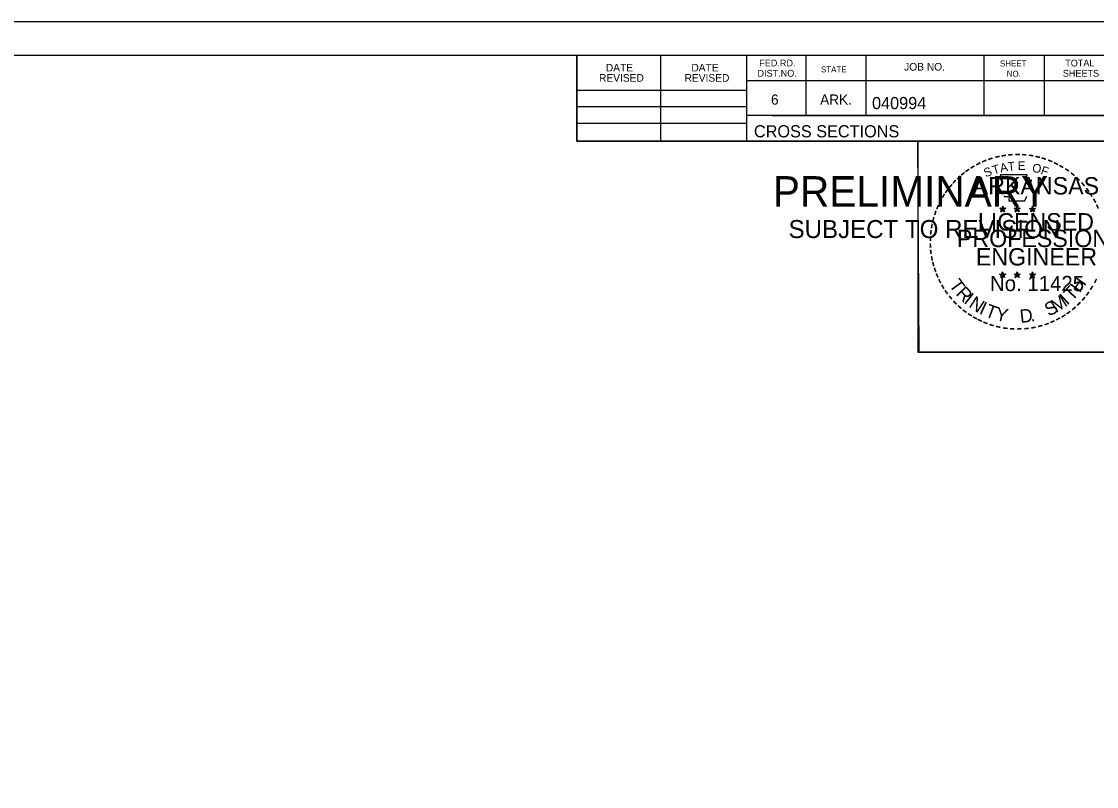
# Model space of a CAD drawing. Extents: x 1381471 to 1382703, y 370300 to 371487.
# Drawn here: x 1382168.2 to 1382292, y 370972.4 to 371060.5 of the extents above; entities that cross this region are included whole.
import ezdxf

# ---------------------------------------------------------------- set-up
doc = ezdxf.new("R2010")
doc.units = 0
doc.layers.add('Level 45', color=7, linetype='Continuous')

msp = doc.modelspace()

# ---------------------------------------------------------------- linework, layer by layer
at = {"layer": 'Level 45'}
for p, q in [((1381966.21, 371060.47), (1382299.55, 371060.47)), ((1381978.61, 371056.58), (1382294.79, 371056.58)), ((1382232.15, 371046.7), (1382232.15, 371056.58)), ((1382241.83, 371046.7), (1382241.83, 371056.58)), ((1382251.69, 371056.58), (1382251.69, 371046.7)), ((1382258.53, 371056.58), (1382258.53, 371049.64)), ((1382265.47, 371056.58), (1382265.47, 371049.64)), ((1382279.05, 371056.58), (1382279.05, 371049.64)), ((1382285.99, 371056.58), (1382285.99, 371049.64)), ((1382294.79, 371053.64), (1382251.69, 371053.64)), ((1382232.15, 371052.56), (1382251.69, 371052.56)), ((1382232.15, 371050.7), (1382251.69, 371050.7)), ((1382232.15, 371048.76), (1382251.69, 371048.76)), ((1382294.79, 371049.64), (1382251.69, 371049.64)), ((1382254.65, 371049.64), (1382294.79, 371049.64)), ((1382294.79, 371046.7), (1382232.15, 371046.7)), ((1382280.88, 371038.96), (1382281.23, 371038.84)), ((1382280.88, 371038.96), (1382281.13, 371038.91)), ((1382280.88, 371038.96), (1382281.12, 371038.83)), ((1382281.01, 371038.55), (1382281.23, 371038.84)), ((1382281.01, 371038.55), (1382281.14, 371038.79)), ((1382281.01, 371038.55), (1382281.23, 371038.76)), ((1382281.23, 371039.21), (1382281.19, 371038.96)), ((1382281.23, 371038.84), (1382281.23, 371039.21)), ((1382281.23, 371039.21), (1382281.28, 371038.96)), ((1382281.57, 371038.96), (1382281.23, 371038.84)), ((1382281.44, 371038.55), (1382281.23, 371038.84)), ((1382281.44, 371038.55), (1382281.23, 371038.76)), ((1382281.57, 371038.96), (1382281.29, 371038.91)), ((1382281.44, 371038.55), (1382281.3, 371038.84)), ((1382281.57, 371038.96), (1382281.37, 371038.85)), ((1382282.55, 371038.96), (1382282.9, 371038.84)), ((1382282.55, 371038.96), (1382282.8, 371038.91)), ((1382282.55, 371038.96), (1382282.79, 371038.83)), ((1382282.68, 371038.55), (1382282.9, 371038.84)), ((1382282.68, 371038.55), (1382282.81, 371038.79)), ((1382282.68, 371038.55), (1382282.9, 371038.76)), ((1382282.9, 371039.21), (1382282.86, 371038.96)), ((1382282.9, 371038.84), (1382282.9, 371039.21)), ((1382282.9, 371039.21), (1382282.95, 371038.96)), ((1382283.24, 371038.96), (1382282.9, 371038.84)), ((1382283.11, 371038.55), (1382282.9, 371038.84)), ((1382283.11, 371038.55), (1382282.9, 371038.76)), ((1382283.24, 371038.96), (1382282.96, 371038.91)), ((1382283.11, 371038.55), (1382282.97, 371038.84)), ((1382283.24, 371038.96), (1382283.04, 371038.85)), ((1382284.31, 371038.94), (1382284.66, 371038.83)), ((1382284.31, 371038.94), (1382284.57, 371038.9)), ((1382284.31, 371038.94), (1382284.55, 371038.82)), ((1382284.45, 371038.54), (1382284.66, 371038.83)), ((1382284.45, 371038.54), (1382284.57, 371038.78)), ((1382284.45, 371038.54), (1382284.66, 371038.75)), ((1382284.66, 371039.2), (1382284.62, 371038.95)), ((1382284.66, 371038.83), (1382284.66, 371039.2)), ((1382284.66, 371039.2), (1382284.71, 371038.95)), ((1382285.01, 371038.94), (1382284.66, 371038.83)), ((1382284.87, 371038.54), (1382284.66, 371038.83)), ((1382284.87, 371038.54), (1382284.66, 371038.75)), ((1382285.01, 371038.94), (1382284.72, 371038.89)), ((1382284.87, 371038.54), (1382284.74, 371038.83)), ((1382285.01, 371038.94), (1382284.8, 371038.84)), ((1382280.87, 371031.38), (1382281.22, 371031.27)), ((1382280.87, 371031.38), (1382281.13, 371031.34)), ((1382280.87, 371031.38), (1382281.11, 371031.26)), ((1382281.01, 371030.97), (1382281.22, 371031.27)), ((1382281.01, 371030.97), (1382281.13, 371031.22)), ((1382281.22, 371031.64), (1382281.18, 371031.38)), ((1382281.22, 371031.27), (1382281.22, 371031.64)), ((1382281.22, 371031.64), (1382281.27, 371031.39)), ((1382281.57, 371031.38), (1382281.22, 371031.27)), ((1382281.44, 371030.97), (1382281.22, 371031.27)), ((1382281.57, 371031.38), (1382281.28, 371031.33)), ((1382281.44, 371030.97), (1382281.3, 371031.27)), ((1382281.57, 371031.38), (1382281.37, 371031.28)), ((1382282.54, 371031.38), (1382282.89, 371031.27)), ((1382282.54, 371031.38), (1382282.8, 371031.34)), ((1382282.54, 371031.38), (1382282.78, 371031.26)), ((1382282.68, 371030.97), (1382282.89, 371031.27)), ((1382282.68, 371030.97), (1382282.8, 371031.22)), ((1382282.89, 371031.64), (1382282.85, 371031.38)), ((1382282.89, 371031.27), (1382282.89, 371031.64)), ((1382282.89, 371031.64), (1382282.94, 371031.39)), ((1382283.24, 371031.38), (1382282.89, 371031.27)), ((1382283.11, 371030.97), (1382282.89, 371031.27)), ((1382283.24, 371031.38), (1382282.95, 371031.33)), ((1382283.11, 371030.97), (1382282.97, 371031.27)), ((1382283.24, 371031.38), (1382283.04, 371031.28)), ((1382284.31, 371031.37), (1382284.66, 371031.26)), ((1382284.31, 371031.37), (1382284.56, 371031.33)), ((1382284.31, 371031.37), (1382284.55, 371031.25)), ((1382284.44, 371030.96), (1382284.66, 371031.26)), ((1382284.66, 371031.63), (1382284.62, 371031.37)), ((1382284.66, 371031.26), (1382284.66, 371031.63)), ((1382284.66, 371031.63), (1382284.71, 371031.38)), ((1382285.01, 371031.37), (1382284.66, 371031.26)), ((1382284.87, 371030.96), (1382284.66, 371031.26)), ((1382285.01, 371031.37), (1382284.72, 371031.32)), ((1382284.87, 371030.96), (1382284.74, 371031.26)), ((1382285.01, 371031.37), (1382284.8, 371031.27)), ((1382281.01, 371030.97), (1382281.22, 371031.19)), ((1382281.44, 371030.97), (1382281.22, 371031.19)), ((1382282.68, 371030.97), (1382282.89, 371031.19)), ((1382283.11, 371030.97), (1382282.89, 371031.19)), ((1382284.44, 371030.96), (1382284.57, 371031.21)), ((1382284.44, 371030.96), (1382284.66, 371031.18)), ((1382284.87, 371030.96), (1382284.66, 371031.18)), ((1382270.83, 371024.24), (1382270.83, 371024.24))]:
    msp.add_line(p, q, dxfattribs=at)
for points in [[(1381966.21, 371060.47), (1382299.55, 371060.47), (1382299.55, 370847.14), (1381966.21, 370847.14)], [(1382212.53, 371056.58), (1382232.15, 371056.58), (1382232.15, 371046.7), (1382248.27, 371046.7), (1382271.46, 371046.7), (1382271.46, 371022.37), (1382294.79, 371022.37), (1382294.79, 370851.12), (1381978.61, 370851.12), (1381978.61, 371056.58)], [(1382271.46, 371046.7), (1382294.67, 371046.7), (1382294.79, 371022.37), (1382271.59, 371022.37)]]:
    msp.add_lwpolyline(points, close=True, dxfattribs=at)
for points in [[(1382280.92, 371042.83), (1382281.19, 371042.01)], [(1382284.43, 371041.91), (1382284.57, 371042.2), (1382283.89, 371042.17), (1382284.04, 371042.83), (1382280.92, 371042.83)], [(1382281.41, 371040.41), (1382281.41, 371040.32), (1382281.97, 371040.3), (1382281.92, 371039.83), (1382283.79, 371039.83), (1382283.99, 371040.37)], [(1382281.23, 371039.21), (1382281.44, 371038.55), (1382280.88, 371038.96), (1382281.57, 371038.96), (1382281.01, 371038.55), (1382281.23, 371039.21)], [(1382282.9, 371039.21), (1382283.11, 371038.55), (1382282.55, 371038.96), (1382283.24, 371038.96), (1382282.68, 371038.55), (1382282.9, 371039.21)], [(1382284.66, 371039.2), (1382284.87, 371038.54), (1382284.31, 371038.94), (1382285.01, 371038.94), (1382284.45, 371038.54), (1382284.66, 371039.2)], [(1382281.22, 371031.64), (1382281.44, 371030.97), (1382280.87, 371031.38), (1382281.57, 371031.38), (1382281.01, 371030.97), (1382281.22, 371031.64)], [(1382282.89, 371031.64), (1382283.11, 371030.97), (1382282.54, 371031.38), (1382283.24, 371031.38), (1382282.68, 371030.97), (1382282.89, 371031.64)], [(1382284.66, 371031.63), (1382284.87, 371030.96), (1382284.31, 371031.37), (1382285.01, 371031.37), (1382284.44, 371030.96), (1382284.66, 371031.63)]]:
    msp.add_lwpolyline(points, dxfattribs=at)
for centre, radius in [((1382281.23, 371038.84), 0.172), ((1382281.23, 371038.84), 0.145), ((1382281.23, 371038.84), 0.116), ((1382281.23, 371038.84), 0.0991), ((1382281.23, 371038.84), 0.0747), ((1382281.23, 371038.84), 0.0495), ((1382281.23, 371038.84), 0.0296), ((1382282.9, 371038.84), 0.172), ((1382282.9, 371038.84), 0.145), ((1382282.9, 371038.84), 0.116), ((1382282.9, 371038.84), 0.0991), ((1382282.9, 371038.84), 0.0747), ((1382282.9, 371038.84), 0.0495), ((1382282.9, 371038.84), 0.0296), ((1382284.66, 371038.83), 0.172), ((1382284.66, 371038.83), 0.145), ((1382284.66, 371038.83), 0.116), ((1382284.66, 371038.83), 0.0991), ((1382284.66, 371038.83), 0.0747), ((1382284.66, 371038.83), 0.0495), ((1382284.66, 371038.83), 0.0296), ((1382281.22, 371031.27), 0.172), ((1382281.22, 371031.27), 0.145), ((1382281.22, 371031.27), 0.116), ((1382281.22, 371031.27), 0.0991), ((1382281.22, 371031.27), 0.0747), ((1382281.22, 371031.27), 0.0495), ((1382281.22, 371031.27), 0.0296), ((1382282.89, 371031.27), 0.172), ((1382282.89, 371031.27), 0.145), ((1382282.89, 371031.27), 0.116), ((1382282.89, 371031.27), 0.0991), ((1382282.89, 371031.27), 0.0747), ((1382282.89, 371031.27), 0.0495), ((1382282.89, 371031.27), 0.0296), ((1382284.66, 371031.26), 0.172), ((1382284.66, 371031.26), 0.145), ((1382284.66, 371031.26), 0.116), ((1382284.66, 371031.26), 0.0991), ((1382284.66, 371031.26), 0.0747), ((1382284.66, 371031.26), 0.0495), ((1382284.66, 371031.26), 0.0296)]:
    msp.add_circle(centre, radius, dxfattribs=at)

# ---------------------------------------------------------------- texts
for s, height, rotation, p in [('FED.RD.', 0.782, 360, (1382253.17, 371055.3)), ('SHEET', 0.684, 360, (1382280.91, 371055.3)), ('TOTAL', 0.782, 360, (1382288.43, 371055.3)), ('DATE', 0.879, 360, (1382235.49, 371054.72)), ('DATE', 0.879, 360, (1382245.35, 371054.72)), ('DIST.NO.', 0.782, 360, (1382252.97, 371054.12)), ('STATE', 0.684, 360, (1382260.29, 371054.62)), ('JOB NO.', 0.879, 360, (1382269.87, 371054.82)), ('NO.', 0.684, 360, (1382281.69, 371054.12)), ('SHEETS', 0.782, 360, (1382288.15, 371054.12)), ('REVISED', 0.879, 360, (1382234.71, 371053.54)), ('REVISED', 0.879, 360, (1382244.57, 371053.54)), ('6', 1.17, 360, (1382254.53, 371050.9)), ('ARK.', 1.172, 360, (1382260.19, 371050.9)), ('040994', 1.4, 360, (1382266.17, 371050.38)), ('CROSS SECTIONS', 1.4, 360, (1382252.56, 371047.13)), ('-', 1.6, 13.6301, (1382280.42, 371044.2)), ('-', 1.6, 10.2193, (1382281.1, 371044.36)), ('-', 1.6, 5.8968, (1382281.82, 371044.47)), ('-', 1.6, 0.1862, (1382282.6, 371044.55)), ('-', 1.6, 357.743, (1382283.32, 371044.53)), ('-', 1.6, 352.1617, (1382284.06, 371044.48)), ('-', 1.6, 347.2049, (1382284.78, 371044.36)), ('-', 1.6, 342.3362, (1382285.42, 371044.21)), ('-', 1.6, 34.0636, (1382277.8, 371043)), ('-', 1.6, 28.7918, (1382278.4, 371043.37)), ('-', 1.6, 24.3072, (1382279.03, 371043.69)), ('S', 1, 21.594, (1382279.27, 371042.51)), ('-', 1.6, 19.1761, (1382279.67, 371043.96)), ('T', 1, 16.4036, (1382280.19, 371042.84)), ('A', 1, 11.2132, (1382281.01, 371043.09)), ('T', 1, 6.0228, (1382281.86, 371043.26)), ('E', 1, 0.8323, (1382282.97, 371043.37)), ('O', 1, 350.4515, (1382284.57, 371043.16)), ('F', 1, 340.0707, (1382285.53, 371042.93)), ('-', 1.6, 337.8551, (1382286.15, 371043.98)), ('-', 1.6, 334.1211, (1382286.78, 371043.71)), ('-', 1.6, 329.6409, (1382287.36, 371043.43)), ('-', 1.6, 325.8627, (1382288.01, 371043.07)), ('PRELIMINARY', 3.5, 360, (1382254.74, 371039.16)), ('-', 1.6, 42.9622, (1382276.32, 371041.81)), ('-', 1.6, 38.9507, (1382276.75, 371042.23)), ('-', 1.6, 36.2317, (1382277.23, 371042.61)), ('ARKANSAS', 2, 360, (1382277.77, 371040.55)), ('-', 1.6, 320.5297, (1382288.62, 371042.64)), ('-', 1.6, 315.5786, (1382289.21, 371042.16)), ('-', 1.6, 54.2325, (1382275.05, 371040.28)), ('-', 1.6, 50.6142, (1382275.47, 371040.85)), ('-', 1.6, 48.423, (1382275.87, 371041.34)), ('-', 1.6, 309.8797, (1382289.78, 371041.61)), ('-', 1.6, 306.6522, (1382290.31, 371041)), ('DWB', 0.01, 360, (1382255.49, 371041.01)), ('-', 1.6, 62.8713, (1382274.41, 371039.14)), ('-', 1.6, 58.0706, (1382274.73, 371039.76)), ('-', 1.4, 303.6753, (1382290.79, 371040.44)), ('-', 1.6, 299.6684, (1382291.11, 371039.83)), ('-', 1.6, 72.3945, (1382273.94, 371037.9)), ('-', 1.6, 67.7743, (1382274.16, 371038.53)), ('DWB', 0.01, 360, (1382281.21, 371038.84)), ('DWB', 0.01, 360, (1382282.88, 371038.84)), ('DWB', 0.01, 360, (1382284.65, 371038.83)), ('-', 1.6, 294.6628, (1382291.44, 371039.22)), ('SUBJECT TO REVISION', 2.0751, 360, (1382256.55, 371035.53)), ('-', 1.6, 75.461, (1382273.74, 371037.19)), ('LICENSED', 2, 360, (1382278.37, 371036.4)), ('-', 1.6, 85.1863, (1382273.53, 371035.78)), ('-', 1.6, 81.2013, (1382273.61, 371036.47)), ('PROFESSIONAL', 2, 360, (1382275.95, 371034.49)), ('-', 1.6, 94.1959, (1382273.54, 371034.36)), ('-', 1.6, 89.0622, (1382273.51, 371035.08)), ('-', 1.6, 98.9479, (1382273.61, 371033.69)), ('ENGINEER', 2, 360, (1382278.13, 371032.37)), ('-', 1.6, 101.7149, (1382273.75, 371032.96)), ('-', 1.6, 105.4578, (1382273.91, 371032.36)), ('-', 1.6, 109.0874, (1382274.13, 371031.73)), ('-', 1.6, 114.0643, (1382274.38, 371031.14)), ('DWB', 0.01, 360, (1382281.21, 371031.27)), ('DWB', 0.01, 360, (1382282.88, 371031.27)), ('DWB', 0.01, 360, (1382284.65, 371031.26)), ('-', 1.6, 115.7289, (1382274.68, 371030.52)), ('-', 1.6, 120.4471, (1382275.04, 371029.93)), ('T', 1.54, 306.0406, (1382274.98, 371030.11)), ('R', 1.54, 314.005, (1382275.75, 371029.06)), ('No. 11425', 1.757, 360, (1382279.76, 371029.42)), ('T', 1.54, 46.6444, (1382289.21, 371028.2)), ('H', 1.54, 54.6088, (1382290.1, 371029.14)), ('-', 1.6, 239.0712, (1382291.12, 371030.42)), ('-', 1.6, 244.6197, (1382291.52, 371031.18)), ('-', 1.6, 125.8934, (1382275.44, 371029.37)), ('-', 1.6, 130.7181, (1382275.91, 371028.82)), ('I', 1.54, 321.9694, (1382276.65, 371028.13)), ('N', 1.54, 326.5002, (1382277.21, 371027.66)), ('M', 1.54, 32.6563, (1382287.37, 371026.88)), ('I', 1.54, 42.1136, (1382288.65, 371027.72)), ('-', 1.6, 231.2538, (1382290.29, 371029.2)), ('-', 1.6, 233.8452, (1382290.72, 371029.77)), ('-', 1.6, 134.2238, (1382276.42, 371028.27)), ('-', 1.6, 138.9338, (1382276.95, 371027.81)), ('I', 1.54, 335.3603, (1382278.42, 371026.87)), ('T', 1.54, 339.8912, (1382279.08, 371026.54)), ('Y', 1.54, 347.8556, (1382280.3, 371026.1)), ('S', 1.54, 26.9312, (1382286.53, 371026.47)), ('-', 1.6, 221.0851, (1382289.29, 371028.13)), ('-', 1.6, 225.7653, (1382289.81, 371028.64)), ('-', 1.6, 144.6463, (1382277.5, 371027.4)), ('-', 1.6, 148.0898, (1382278.07, 371027.03)), ('-', 1.6, 151.5704, (1382278.64, 371026.71)), ('D', 1.54, 6.3969, (1382283.28, 371025.74)), ('-', 1.6, 207.3568, (1382287.65, 371026.93)), ('-', 1.6, 212.2491, (1382288.21, 371027.27)), ('-', 1.6, 215.7363, (1382288.74, 371027.66)), ('-', 1.6, 154.6002, (1382279.17, 371026.46)), ('-', 1.6, 158.5612, (1382279.79, 371026.21)), ('-', 1.6, 162.7983, (1382280.48, 371025.99)), ('-', 1.6, 167.5555, (1382281.19, 371025.83)), ('-', 1.6, 173.1155, (1382281.96, 371025.72)), ('-', 1.6, 176.5183, (1382282.71, 371025.67)), ('-', 1.6, 181.5918, (1382283.46, 371025.69)), ('-', 1.6, 185.8167, (1382284.27, 371025.76)), ('-', 1.6, 191.2858, (1382285, 371025.89)), ('.', 1.54, 13.7642, (1382284.48, 371025.87)), ('-', 1.6, 195.4743, (1382285.73, 371026.09)), ('-', 1.6, 200.7184, (1382286.41, 371026.33)), ('-', 1.6, 204.2516, (1382287.03, 371026.61))]:
    msp.add_text(s, height=height, rotation=rotation, dxfattribs=at).set_placement(p)

doc.saveas('drawing.dxf')
